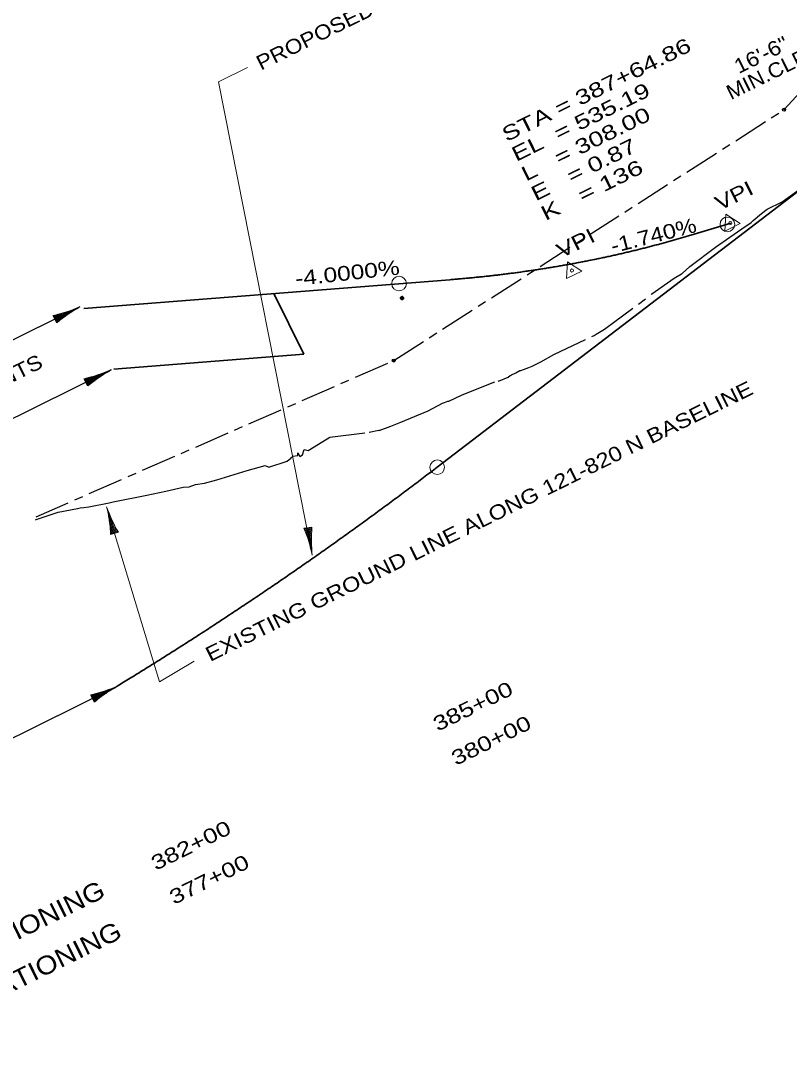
# Model space of a CAD drawing. Extents: x 2356431 to 2371438, y 6972864 to 6982525.
# Drawn here: x 2366570 to 2367303, y 6977228 to 6978229 of the extents above; entities that cross this region are included whole.
import ezdxf
from ezdxf.enums import TextEntityAlignment as Align

# ---------------------------------------------------------------- set-up
doc = ezdxf.new("R2010")
doc.units = 0
doc.header["$LTSCALE"] = 5.6
doc.header["$PDMODE"] = 32
doc.header["$PDSIZE"] = 2.8
doc.linetypes.add('LONG_DASH_SHORT_DASH', pattern=[9.9, 6, -1.2, 1.5, -1.2])
doc.linetypes.add('LONG_DASHED', pattern=[7.5, 6, -1.5])
for name, color, linetype, lineweight in [('1', 7, 'Continuous', 25), ('2', 7, 'Continuous', 35), ('4', 7, 'LONG_DASHED', 35), ('44', 7, 'Continuous', 13), ('52', 7, 'Continuous', 25), ('53', 7, 'Continuous', 13), ('61', 7, 'Continuous', 13)]:
    doc.layers.add(name, color=color, linetype=linetype, lineweight=lineweight)

msp = doc.modelspace()

# ---------------------------------------------------------------- linework, layer by layer
at = {"layer": '1'}
for p, q in [((2366601.982, 6977943.985), (2366624.512, 6977955.114)), ((2366603.62, 6977940.668), (2366600.229, 6977947.536)), ((2366600.653, 6977946.675), (2366604.923, 6977948.785)), ((2366601.096, 6977945.778), (2366609.816, 6977950.085)), ((2366601.54, 6977944.882), (2366616.978, 6977952.508)), ((2366602.424, 6977943.089), (2366615.605, 6977949.599)), ((2366602.868, 6977942.193), (2366610.537, 6977945.98)), ((2366603.311, 6977941.296), (2366606.153, 6977942.699)), ((2366631.706, 6977883.758), (2366654.236, 6977894.887)), ((2366633.344, 6977880.441), (2366629.953, 6977887.309)), ((2366630.377, 6977886.448), (2366634.647, 6977888.558)), ((2366630.82, 6977885.551), (2366639.54, 6977889.858)), ((2366631.264, 6977884.655), (2366646.702, 6977892.281)), ((2366632.148, 6977882.862), (2366645.329, 6977889.372)), ((2366632.592, 6977881.966), (2366640.261, 6977885.753)), ((2366633.035, 6977881.069), (2366635.877, 6977882.472)), ((2366637.722, 6977581.809), (2366660.253, 6977592.938)), ((2366639.577, 6977578.599), (2366636.185, 6977585.466)), ((2366636.394, 6977584.5), (2366640.664, 6977586.61)), ((2366636.836, 6977583.603), (2366645.555, 6977587.91)), ((2366637.279, 6977582.706), (2366652.718, 6977590.333)), ((2366638.165, 6977580.913), (2366651.344, 6977587.423)), ((2366638.608, 6977580.017), (2366646.277, 6977583.804)), ((2366639.051, 6977579.12), (2366641.892, 6977580.524))]:
    msp.add_line(p, q, dxfattribs=at)
for centre, start, end in [((2366568.335, 6978088.403), 282.75754, 293.44359), ((2366696.106, 6977829.731), 119.1307, 129.81675), ((2366598.058, 6978028.176), 282.75754, 293.44359), ((2366725.83, 6977769.505), 119.1307, 129.81675), ((2366604.29, 6977726.332), 282.75754, 293.44359), ((2366732.061, 6977467.66), 119.1307, 129.81675)]:
    msp.add_arc(centre, 144.431, start, end, dxfattribs=at)
at = {"layer": '2'}
msp.add_line((2366966.766, 6977802.834), (2368267.334, 6978797.502), dxfattribs=at)
at = {"layer": '2', "lineweight": 13}
for p, q in [((2366757.958, 6978170.739), (2366847.528, 6977718.769)), ((2366701.733, 6977598.041), (2366651.249, 6977765.102)), ((2366839.648, 6977744.487), (2366847.218, 6977745.664)), ((2366662.478, 6977740.66), (2366655.132, 6977738.486))]:
    msp.add_line(p, q, dxfattribs=at)
at = {"layer": '2', "lineweight": 25}
msp.add_line((2366295.248, 6977412.955), (2366661.345, 6977593.635), dxfattribs=at)
at = {"layer": '2', "lineweight": 13}
for centre, start, end in [((2366510.894, 6977731.033), 2.95802, 13.64407), ((2366787.538, 6977812.914), 199.33119, 210.01724), ((2366706.092, 6977689.505), 11.68993, 22.37598), ((2366991.168, 6977733.873), 175.31677, 186.00282)]:
    msp.add_arc(centre, 144.431, start, end, dxfattribs=at)
at = {"layer": '2'}
msp.add_spline([(2366661.281, 6977593.763), (2366673.674, 6977601.34), (2366687.349, 6977609.785), (2366700.99, 6977618.298), (2366714.598, 6977626.878), (2366728.171, 6977635.528), (2366741.712, 6977644.245), (2366755.219, 6977653.029), (2366768.692, 6977661.883), (2366782.132, 6977670.804), (2366795.538, 6977679.792), (2366808.91, 6977688.85), (2366822.25, 6977697.974), (2366835.555, 6977707.167), (2366848.827, 6977716.427), (2366862.066, 6977725.757), (2366875.271, 6977735.153), (2366888.442, 6977744.618), (2366901.58, 6977754.151), (2366914.684, 6977763.751), (2366927.755, 6977773.421), (2366940.792, 6977783.157), (2366953.796, 6977792.961), (2366966.766, 6977802.834)], degree=3, dxfattribs=at)
at = {"layer": '4'}
msp.add_point((2366933.246, 6977964.299), dxfattribs=at)
at = {"layer": '44'}
for p, q in [((2366757.958, 6978170.739), (2366785.725, 6978184.444)), ((2366658.93, 6977739.609), (2366651.798, 6977763.705)), ((2366657.97, 6977739.326), (2366653.084, 6977755.839)), ((2366659.889, 6977739.893), (2366655.717, 6977753.989)), ((2366657.011, 6977739.042), (2366654.252, 6977748.367)), ((2366656.052, 6977738.758), (2366654.702, 6977743.325)), ((2366660.847, 6977740.177), (2366658.421, 6977748.38)), ((2366661.807, 6977740.461), (2366660.908, 6977743.501)), ((2366840.341, 6977744.594), (2366840.828, 6977741.462)), ((2366841.33, 6977744.749), (2366842.644, 6977736.297)), ((2366842.316, 6977744.903), (2366844.578, 6977730.378)), ((2366843.305, 6977745.056), (2366847.17, 6977720.226)), ((2366844.294, 6977745.209), (2366846.941, 6977728.195)), ((2366845.283, 6977745.363), (2366846.776, 6977735.755)), ((2366846.27, 6977745.517), (2366847.002, 6977740.811))]:
    msp.add_line(p, q, dxfattribs=at)
at = {"layer": '52', "lineweight": 13}
for p, q in [((2367242.327, 6978044.322), (2367241.346, 6978028.195)), ((2367242.327, 6978044.322), (2367255.806, 6978035.414)), ((2367241.346, 6978028.195), (2367255.806, 6978035.414)), ((2367091.207, 6977999), (2367090.226, 6977982.873)), ((2367091.207, 6977999), (2367104.686, 6977990.092)), ((2367090.226, 6977982.873), (2367104.686, 6977990.092)), ((2366701.733, 6977598.041), (2366734.765, 6977617.675))]:
    msp.add_line(p, q, dxfattribs=at)
at = {"layer": '52', "linetype": 'LONG_DASH_SHORT_DASH'}
msp.add_line((2366583.948, 6977755.451), (2366925.324, 6977904.629), dxfattribs=at)
for points in [[(2366925.324, 6977904.629), (2367297.777, 6978144.207), (2367392.228, 6978246.582)], [(2366583.399, 6977752.584), (2366584.162, 6977752.778), (2366605.008, 6977760.022), (2366623.434, 6977763.359), (2366623.549, 6977763.397), (2366626.013, 6977763.984), (2366629.609, 6977764.427), (2366634.208, 6977765.027), (2366653.816, 6977768.95), (2366655.021, 6977768.993), (2366657.616, 6977769.678), (2366689.595, 6977776.17), (2366707.872, 6977780.1), (2366724.179, 6977783.89), (2366730.165, 6977784.189), (2366736.106, 6977786.294), (2366744.7, 6977787.635), (2366756.611, 6977790.728), (2366785.472, 6977799.651), (2366802.444, 6977804.487), (2366806.169, 6977802.836), (2366823.623, 6977808.685), (2366827.051, 6977811.59), (2366827.159, 6977811.71), (2366827.308, 6977811.86), (2366827.49, 6977812.034), (2366827.704, 6977812.234), (2366827.96, 6977812.459), (2366828.235, 6977812.694), (2366828.528, 6977812.937), (2366828.833, 6977813.176), (2366829.043, 6977813.338), (2366833.678, 6977813.866), (2366833.65, 6977816.455), (2366833.713, 6977816.485), (2366833.775, 6977816.516), (2366835.238, 6977813.8), (2366835.627, 6977813.081), (2366838.253, 6977814.583), (2366839.93, 6977819.658), (2366843.499, 6977818.618), (2366845.359, 6977819.663), (2366864.316, 6977831.482), (2366901.837, 6977836.256), (2366911.038, 6977838.105), (2366911.1, 6977838.048), (2366911.232, 6977837.917), (2366922.598, 6977842.046), (2366932.034, 6977845.77), (2366958.082, 6977856.778), (2366971.87, 6977863.863), (2366973.802, 6977864.535), (2366977.049, 6977865.842), (2366977.209, 6977865.902), (2366977.256, 6977865.919), (2366978.014, 6977865.876), (2366990.642, 6977871.899), (2367024.855, 6977885.683), (2367024.867, 6977885.747), (2367025.291, 6977884.957), (2367034.565, 6977888.693), (2367036.463, 6977890.518), (2367037.324, 6977890.762), (2367037.393, 6977890.804), (2367037.66, 6977890.918), (2367037.986, 6977891.07), (2367038.407, 6977891.28), (2367039.009, 6977891.596), (2367039.953, 6977892.101), (2367041.728, 6977893.07), (2367045.543, 6977895.168), (2367046.509, 6977895.222), (2367046.606, 6977895.205), (2367054.139, 6977898.042), (2367057.521, 6977899.301), (2367065.618, 6977903.389), (2367077.969, 6977910.381), (2367116.435, 6977928.471), (2367118.505, 6977929.993), (2367126.562, 6977934.479), (2367171.688, 6977968.269), (2367192.819, 6977983.275), (2367200.032, 6977987.437), (2367200.416, 6977987.789), (2367207.728, 6977994.484), (2367232.357, 6978012.798), (2367245.986, 6978022.442), (2367257.465, 6978030.411), (2367266.385, 6978036.493), (2367268.206, 6978038.293), (2367276.236, 6978045.162), (2367281.83, 6978049.304), (2367295.987, 6978056.276), (2367340.997, 6978088.494)]]:
    msp.add_lwpolyline(points, dxfattribs=at)
at = {"layer": '52', "lineweight": 13}
for centre, radius in [((2367243.727, 6978034.658), 7), ((2367246.485, 6978035.968), 1.5), ((2366930.349, 6977978.157), 7), ((2367095.364, 6977990.648), 1.5)]:
    msp.add_circle(centre, radius, dxfattribs=at)
at = {"layer": '52'}
for p in [(2367297.777, 6978144.207), (2366925.324, 6977904.629)]:
    msp.add_point(p, dxfattribs=at)
at = {"layer": '53', "lineweight": 35}
for p, q in [((2367208.764, 6978024.353), (2367246.965, 6978035.792)), ((2366629.473, 6977954.223), (2366978.764, 6977981.851)), ((2366839.453, 6977910.644), (2366810.864, 6977968.57)), ((2366658.061, 6977896.296), (2366839.453, 6977910.644))]:
    msp.add_line(p, q, dxfattribs=at)
at = {"layer": '53', "lineweight": 25}
for p, q in [((2366625.795, 6977955.893), (2366486.492, 6977887.142)), ((2366655.519, 6977895.666), (2366516.216, 6977826.915))]:
    msp.add_line(p, q, dxfattribs=at)
at = {"layer": '53', "lineweight": 35}
msp.add_spline([(2366978.764, 6977981.851), (2366983.59, 6977982.243), (2366988.408, 6977982.653), (2366993.217, 6977983.081), (2366998.016, 6977983.529), (2367002.806, 6977983.995), (2367007.586, 6977984.481), (2367012.357, 6977984.985), (2367017.119, 6977985.508), (2367021.872, 6977986.048), (2367026.615, 6977986.609), (2367031.349, 6977987.187), (2367036.074, 6977987.784), (2367040.79, 6977988.4), (2367045.497, 6977989.035), (2367050.194, 6977989.689), (2367054.882, 6977990.361), (2367059.561, 6977991.052), (2367064.23, 6977991.761), (2367068.89, 6977992.491), (2367073.541, 6977993.238), (2367078.183, 6977994.003), (2367082.816, 6977994.788), (2367087.439, 6977995.591), (2367092.053, 6977996.413), (2367096.658, 6977997.254), (2367101.252, 6977998.112), (2367105.838, 6977998.991), (2367110.415, 6977999.888), (2367114.983, 6978000.803), (2367119.541, 6978001.737), (2367124.09, 6978002.691), (2367128.63, 6978003.663), (2367133.161, 6978004.652), (2367137.682, 6978005.662), (2367142.195, 6978006.689), (2367146.697, 6978007.737), (2367151.191, 6978008.802), (2367155.675, 6978009.886), (2367160.15, 6978010.989), (2367164.616, 6978012.109), (2367169.072, 6978013.249), (2367173.519, 6978014.409), (2367177.957, 6978015.586), (2367182.386, 6978016.782), (2367186.805, 6978017.998), (2367191.215, 6978019.231), (2367195.616, 6978020.484), (2367200.008, 6978021.754), (2367204.391, 6978023.044), (2367208.764, 6978024.353)], degree=3, dxfattribs=at)
at = {"layer": '61'}
msp.add_circle((2366966.766, 6977802.834), 7, dxfattribs=at)

# ---------------------------------------------------------------- texts
at = {"layer": '1'}
for s, width, p in [('16\'-6"', 1.15, (2367279.078, 6978190.261)), ('MIN.CLR.', 1.1, (2367287.637, 6978173.296))]:
    msp.add_text(s, height=14, rotation=26.268, dxfattribs=dict(at, width=width)).set_placement(p, align=Align.CENTER)
at = {"layer": '2'}
for s, height, width, p in [('PROPOSED 820S-121 PROFILE', 14, 1.15, (2366941.777, 6978252.151)), ('IDENTICAL POINTS', 14, 1.15, (2366502.669, 6977854.695)), ('EXISTING GROUND LINE ALONG 121-820 N BASELINE', 14, 1.2, (2367009.823, 6977745.018)), ('121-820N STATIONING', 17.5, 1.15, (2366521.521, 6977329.097)), ('820S-121 STATIONING', 17.5, 1.15, (2366538.107, 6977290.312))]:
    msp.add_text(s, height=height, rotation=26.268, dxfattribs=dict(at, width=width)).set_placement(p, align=Align.CENTER)
for s, rotation, width, p in [('-1.740%', 14.302, 1.2, (2367134.379, 6978006.996)), ('-4.0000%', 6.302, 1.25, (2366831.949, 6977975.822))]:
    msp.add_text(s, height=14, rotation=rotation, dxfattribs=dict(at, width=width)).set_placement(p)
at = {"layer": '52', "width": 1.25}
for p in [(2367253.183, 6978055.849), (2367102.061, 6978010.528)]:
    msp.add_text('VPI', height=14, rotation=26.531, dxfattribs=at).set_placement(p, align=Align.CENTER)
at = {"layer": '53'}
for s, width, p in [('STA = 387+64.86 ', 1.35, (2367032.931, 6978113.116)), ('EL  = 535.19             ', 1.35, (2367042.224, 6978094.285)), ('L   = 308.00      ', 1.35, (2367051.518, 6978075.454)), ('E   = 0.87', 1.35, (2367060.812, 6978056.623)), ('K   = 136             ', 1.4, (2367070.106, 6978037.792))]:
    msp.add_text(s, height=14, rotation=26.268, dxfattribs=dict(at, width=width)).set_placement(p)
at = {"layer": '53', "width": 1.3}
for s, p in [('385+00', (2367003.91, 6977568.323)), ('380+00', (2367021.356, 6977535.726)), ('382+00', (2366734.877, 6977435.546)), ('377+00', (2366752.274, 6977402.925))]:
    msp.add_text(s, height=14, rotation=26.268, dxfattribs=at).set_placement(p, align=Align.CENTER)

doc.saveas('drawing.dxf')
